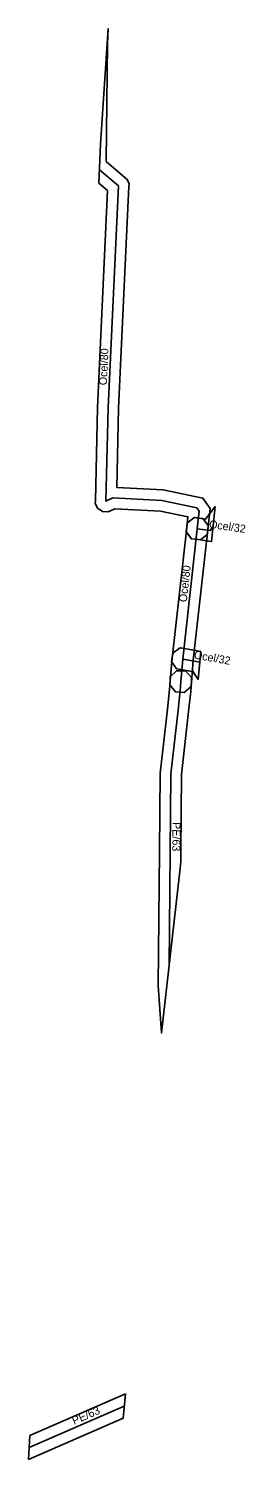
# Model space of a CAD drawing. Extents: x -569518 to -569136, y -1179473 to -1178304.
# Drawn here: x -569518.1 to -569497.7, y -1179472.6 to -1179338.5 of the extents above; entities that cross this region are included whole.
import ezdxf

# ---------------------------------------------------------------- set-up
doc = ezdxf.new("R2010")
doc.units = 0
for name, color, linetype in [('1', 7, 'Continuous'), ('24', 7, 'Continuous'), ('30', 7, 'Continuous')]:
    doc.layers.add(name, color=color, linetype=linetype)

msp = doc.modelspace()

# ---------------------------------------------------------------- linework, layer by layer
at = {"layer": '1'}
for points in [[(-569511.34, -1179349.33), (-569510.63, -1179338.51), (-569510.69, -1179339.95), (-569510.82, -1179350.95), (-569509.03, -1179352.49), (-569508.85, -1179352.64), (-569508.67, -1179353.07), (-569508.68, -1179353.3), (-569509.65, -1179374.09), (-569509.81, -1179381.52), (-569505.47, -1179381.74), (-569501.74, -1179382.52), (-569501.04, -1179383.48), (-569501.28, -1179385.51), (-569501.33, -1179385.92), (-569501.97, -1179386.43), (-569502.39, -1179386.38), (-569502.8, -1179386.33), (-569503.31, -1179385.69), (-569503.26, -1179385.28), (-569503.15, -1179384.27), (-569505.73, -1179383.73), (-569510, -1179383.51), (-569510.43, -1179383.7), (-569510.67, -1179383.81), (-569511.18, -1179383.77), (-569511.39, -1179383.62), (-569511.61, -1179383.48), (-569511.85, -1179383.03), (-569511.84, -1179382.77), (-569511.65, -1179374.03), (-569510.7, -1179353.69), (-569511.52, -1179352.99)], [(-569500.6, -1179383.29), (-569500.92, -1179386.59), (-569501.18, -1179386.55), (-569502.41, -1179386.38), (-569502.82, -1179386.32), (-569503.32, -1179385.66), (-569503.26, -1179385.25), (-569503.2, -1179384.84), (-569502.54, -1179384.34), (-569502.13, -1179384.4), (-569501.49, -1179384.49)], [(-569504.85, -1179400.03), (-569504.82, -1179399.62), (-569504.62, -1179397.51), (-569503.26, -1179385.28), (-569503.22, -1179384.87), (-569502.57, -1179384.35), (-569502.16, -1179384.4), (-569501.75, -1179384.44), (-569501.23, -1179385.09), (-569501.28, -1179385.5), (-569502.64, -1179397.71), (-569502.82, -1179399.8), (-569502.86, -1179400.21), (-569503.5, -1179400.74), (-569503.91, -1179400.71), (-569504.32, -1179400.67)], [(-569501.92, -1179396.9), (-569502.17, -1179399.52), (-569502.61, -1179398.86), (-569502.6, -1179398.81), (-569503.8, -1179398.59), (-569504.21, -1179398.52), (-569504.69, -1179397.84), (-569504.61, -1179397.44), (-569504.54, -1179397.03), (-569503.86, -1179396.55), (-569503.46, -1179396.62)], [(-569503.93, -1179417.77), (-569505.62, -1179432.65), (-569505.93, -1179428.22), (-569505.81, -1179415.63), (-569505.75, -1179408.31), (-569505.06, -1179402.29), (-569504.86, -1179400.45), (-569504.83, -1179400.12), (-569504.82, -1179399.69), (-569504.81, -1179399.27), (-569504.21, -1179398.7), (-569503.8, -1179398.71), (-569503.38, -1179398.72), (-569502.81, -1179399.32), (-569502.82, -1179399.73), (-569502.83, -1179400.22), (-569502.86, -1179400.65), (-569503.08, -1179402.51), (-569503.75, -1179408.43), (-569503.81, -1179415.65), (-569503.82, -1179416.61)], [(-569509.01, -1179466.49), (-569509.24, -1179468.77), (-569518.11, -1179472.63), (-569517.98, -1179470.39)]]:
    msp.add_lwpolyline(points, close=True, dxfattribs=at)
at = {"layer": '24'}
for points in [[(-569502.27, -1179385.39), (-569502.08, -1179383.75), (-569502.32, -1179383.42), (-569505.6, -1179382.73), (-569510.19, -1179382.5), (-569510.84, -1179382.79), (-569510.65, -1179374.06), (-569509.68, -1179353.25), (-569511.46, -1179351.73)], [(-569503.82, -1179399.71), (-569503.63, -1179397.61), (-569502.27, -1179385.39)], [(-569502.27, -1179385.39), (-569501.04, -1179385.56), (-569500.79, -1179385.22)], [(-569503.63, -1179397.61), (-569502.01, -1179397.9)], [(-569503.82, -1179399.71), (-569503.83, -1179400.17), (-569503.86, -1179400.55), (-569504.07, -1179402.4), (-569504.75, -1179408.37), (-569504.81, -1179415.64), (-569504.91, -1179426.41)], [(-569509.13, -1179467.63), (-569518.05, -1179471.51)]]:
    msp.add_lwpolyline(points, dxfattribs=at)

# ---------------------------------------------------------------- texts
at = {"layer": '30'}
for s, rotation, p in [('Ocel/80', 87.3312, (-569510.76, -1179371.95)), ('Ocel/32', 352.1309, (-569501.19, -1179385.31)), ('Ocel/80', 83.6495, (-569503.26, -1179392.3)), ('Ocel/32', 349.992, (-569502.62, -1179397.55)), ('PE/63', 269.5271, (-569504.59, -1179412.89)), ('PE/63', 23.5151, (-569513.83, -1179469.39))]:
    msp.add_text(s, height=0.75, rotation=rotation, dxfattribs=at).set_placement(p)

doc.saveas('drawing.dxf')
